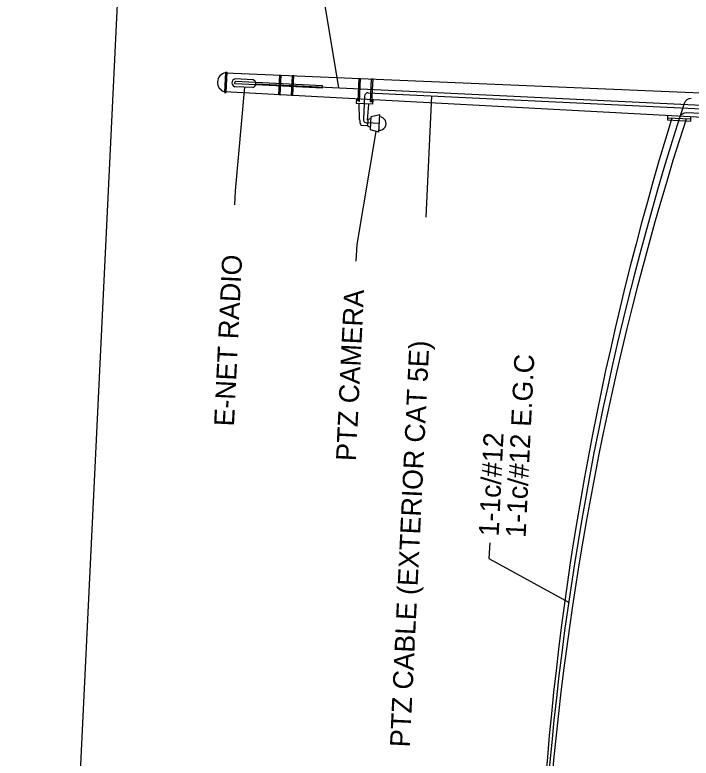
# Model space of a CAD drawing. Extents: x 590069 to 611209, y 383148 to 419683.
# Drawn here: x 610410.4 to 610576.8, y 418965.4 to 419148.2 of the extents above; entities that cross this region are included whole.
import ezdxf

# ---------------------------------------------------------------- set-up
doc = ezdxf.new("R2010")
doc.units = 0
doc.layers.add('NO PLOT CELL', color=7, linetype='Continuous')
doc.layers.add('T_Drafting', color=7, linetype='Continuous')

msp = doc.modelspace()

# ---------------------------------------------------------------- linework, layer by layer
at = {"layer": 'NO PLOT CELL'}
msp.add_lwpolyline([(610410.43, 418628.74), (611035.09, 418598.61), (611078.28, 419493.98), (611027.13, 419496.45), (611030.04, 419556.78), (610902.07, 419563.35), (610902.07, 419563.35), (610583.92, 419578.7), (610486.35, 419585.78), (610487.36, 419606.71), (610496.65, 419606.26), (610487.36, 419606.71), (610481.63, 419487.9), (610451.93, 419489.33)], close=True, dxfattribs=at)
msp.add_lwpolyline([(610410.43, 418628.74), (611035.09, 418598.61), (611078.28, 419493.98), (611027.13, 419496.45), (611030.04, 419556.78), (610902.07, 419563.35), (610902.07, 419563.35), (610583.92, 419578.7), (610486.35, 419585.78), (610487.36, 419606.71), (610496.65, 419606.26), (610487.36, 419606.71), (610481.63, 419487.9), (610451.93, 419489.33)], close=True, dxfattribs=at)
at = {"layer": 'T_Drafting'}
for p, q in [((610483.17, 419172.24), (610490.04, 419130.24)), ((610462.25, 419134.07), (610462.01, 419129.11)), ((610462.24, 419133.93), (610811.93, 419119.1)), ((610462.25, 419134.07), (610462.69, 419134.05)), ((610462.45, 419129.09), (610462.69, 419134.05)), ((610464.58, 419131.19), (610464.61, 419131.75)), ((610469.7, 419131.5), (610464.61, 419131.75)), ((610469.05, 419132.21), (610464.64, 419132.42)), ((610475.39, 419128.48), (610475.62, 419133.38)), ((610475.62, 419133.38), (610475.97, 419133.37)), ((610475.74, 419128.46), (610475.97, 419133.37)), ((610478.46, 419128.32), (610478.7, 419133.25)), ((610478.7, 419133.25), (610479.05, 419133.24)), ((610478.81, 419128.3), (610479.05, 419133.24)), ((610494.86, 419126.92), (610495.13, 419132.55)), ((610495.13, 419132.55), (610495.48, 419132.54)), ((610495.21, 419126.9), (610495.48, 419132.54)), ((610497.94, 419126.77), (610498.21, 419132.42)), ((610498.21, 419132.42), (610498.56, 419132.41)), ((610498.29, 419126.75), (610498.56, 419132.41)), ((610468.95, 419130.28), (610464.55, 419130.49)), ((610469.68, 419130.95), (610464.58, 419131.19)), ((610464.73, 419104.91), (610467.01, 419130.37)), ((610486.12, 419130.15), (610469.68, 419130.95)), ((610486.14, 419130.71), (610469.7, 419131.5)), ((610469.73, 419131.22), (610794.83, 419115.54)), ((610486.12, 419130.15), (610486.14, 419130.71)), ((610462.01, 419129.11), (610462.45, 419129.09)), ((610811.51, 419110.36), (610462.02, 419129.25)), ((610475.74, 419128.46), (610475.39, 419128.48)), ((610478.81, 419128.3), (610478.46, 419128.32)), ((610496.46, 419128.18), (610496.19, 419122.53)), ((610497.38, 419129.01), (610795.24, 419114.65)), ((610511.62, 419098.39), (610513.06, 419128.26)), ((610494.52, 419126.38), (610494.57, 419127.49)), ((610498.54, 419126.18), (610494.52, 419126.38)), ((610495.21, 419126.9), (610494.86, 419126.92)), ((610495.25, 419122.4), (610495.18, 419126.34)), ((610497.23, 419122.3), (610497.56, 419126.23)), ((610498.29, 419126.75), (610497.94, 419126.77)), ((610498.54, 419126.18), (610498.6, 419127.27)), ((610498.07, 419122.65), (610497.38, 419122.44)), ((610497.94, 419119.92), (610498.1, 419123.17)), ((610498.1, 419123.17), (610500.21, 419123.63)), ((610500.01, 419119.29), (610500.21, 419123.63)), ((610571.02, 419123.36), (610570.97, 419122.32)), ((610576.66, 419122.48), (610571, 419122.79)), ((610802.38, 419113.16), (610575.71, 419124.09)), ((610576.69, 419123.06), (610576.64, 419122.04)), ((610497.3, 419120.9), (610495.62, 419120.98)), ((610500.11, 419121.46), (610497.02, 419121.61)), ((610497.37, 419122.3), (610497.23, 419122.3)), ((610497.3, 419120.76), (610497.38, 419122.44)), ((610497.3, 419120.9), (610497.37, 419122.3)), ((610497.97, 419120.48), (610497.3, 419120.76)), ((610570.97, 419122.32), (610576.64, 419122.04)), ((610494.62, 419091.7), (610499.35, 419119.49)), ((610500.01, 419119.29), (610497.94, 419119.92)), ((610464.56, 419101.48), (610464.73, 419104.91)), ((610494.43, 419087.58), (610494.62, 419091.7)), ((610527.26, 419018.29), (610527.07, 419014.46)), ((610527.07, 419014.46), (610546.68, 419003.7))]:
    msp.add_line(p, q, dxfattribs=at)
for centre, radius, start, end in [((610462.71, 419131.56), 2.42, 101.1856, 253.2917), ((610464.83, 419131.44), 0.994, 100.9394, 253.5378), ((610468.73, 419131.26), 1, 282.6724, 71.8048), ((610497.34, 419128.14), 0.875, 87.2386, 177.2386), ((611286.7, 418897.03), 747.67, 162.13732, 175.73913), ((610576.74, 419125.83), 1.75, 87.2386, 162.1373), ((610497.06, 419122.49), 0.875, 177.2386, 267.2386), ((610500.14, 419121.44), 1.63, 266.2177, 88.2595), ((611287.5, 418901.75), 748.77, 162.83539, 175.92654), ((611289.43, 418892.8), 749.92, 162.16014, 175.24259), ((610575.63, 419122.34), 1.75, 87.2386, 162.4186), ((610497.99, 419122.36), 2.74, 179.2231, 210.2828)]:
    msp.add_arc(centre, radius, start, end, dxfattribs=at)

# ---------------------------------------------------------------- texts
for s, p in [('E-NET RADIO', (610464.33, 419046.9)), ('PTZ CAMERA', (610494.33, 419038.36)), ('PTZ CABLE (EXTERIOR CAT 5E)', (610507.6, 418967.96)), ('1-1c/#12 E.G.C', (610536.09, 419019.52)), ('1-1c/#12', (610529.46, 419019.84))]:
    msp.add_text(s, height=4.9, rotation=87.2386, dxfattribs=at).set_placement(p)

doc.saveas('drawing.dxf')
